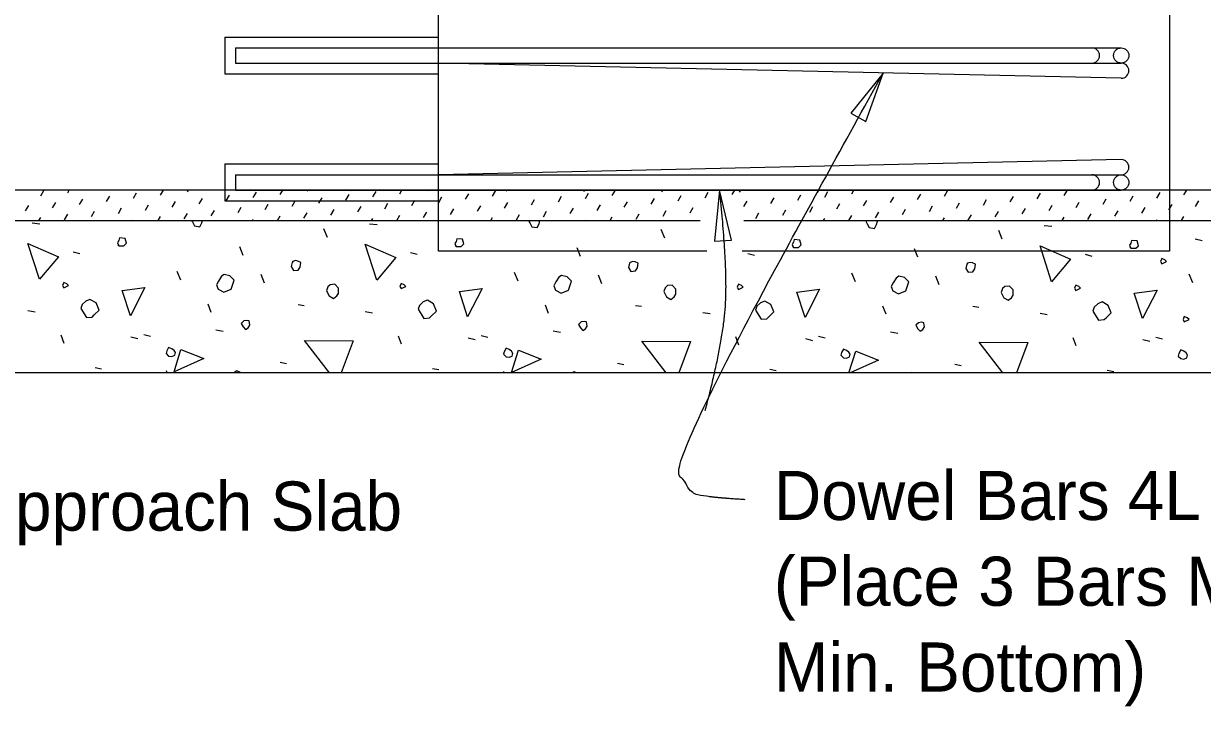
# Model space of a CAD drawing. Extents: x 21587 to 21656.3, y 56114 to 56157.2.
# Drawn here: x 21619.146 to 21623.985, y 56131.933 to 56134.734 of the extents above; entities that cross this region are included whole.
import ezdxf

# ---------------------------------------------------------------- set-up
doc = ezdxf.new("R2010")
doc.units = 0
for name, color, linetype in [('AdhocPoint_dp', 7, 'Continuous'), ('PlotBorder_dp', 7, 'Continuous'), ('SheetBorder_dp', 7, 'Continuous'), ('SheetLines_dp', 7, 'Continuous'), ('SubStrConc', 7, 'Continuous'), ('SubStrConc_h', 7, 'Continuous'), ('TextMisc', 7, 'Continuous')]:
    doc.layers.add(name, color=color, linetype=linetype)

msp = doc.modelspace()

# ---------------------------------------------------------------- linework, layer by layer
at = {"layer": 'AdhocPoint_dp'}
for p, q in [((21619.9721, 56134.6787), (21619.9721, 56134.5273)), ((21619.9721, 56134.6787), (21620.8499, 56134.6787)), ((21619.9721, 56134.5273), (21620.8499, 56134.5273)), ((21619.9721, 56134.1579), (21620.8499, 56134.1579)), ((21619.9721, 56134.1579), (21619.9721, 56134.0065)), ((21624.3563, 56134.0511), (21613.608, 56134.0511)), ((21619.9721, 56134.0065), (21620.8499, 56134.0065)), ((21613.608, 56133.926), (21621.9231, 56133.926)), ((21622.1027, 56133.926), (21624.3563, 56133.926)), ((21624.3563, 56133.301), (21618.8279, 56133.301))]:
    msp.add_line(p, q, dxfattribs=at)
at = {"layer": 'PlotBorder_dp'}
for points in [[(21622.6748, 56134.5311), (21622.5424, 56134.3666), (21622.604, 56134.3322)], [(21622.0034, 56134.0509), (21621.9823, 56133.8408), (21622.0527, 56133.8455)]]:
    msp.add_lwpolyline(points, close=True, dxfattribs=at)
for points in [[(21622.109, 56132.7809), (21621.9358, 56132.7915), (21621.8722, 56132.8163), (21621.805, 56132.9754), (21622.6748, 56134.5311)], [(21621.9446, 56133.1469), (21622.0135, 56133.4067), (21622.0391, 56133.7156), (21622.0034, 56134.0509)]]:
    msp.add_open_spline(points, degree=2, dxfattribs=at)
at = {"layer": 'SheetLines_dp'}
for p, q in [((21620.0165, 56134.6343), (21623.652, 56134.6343)), ((21620.0165, 56134.6343), (21620.0165, 56134.5718)), ((21620.0165, 56134.5718), (21623.652, 56134.5718)), ((21623.652, 56134.5094), (21620.8499, 56134.5718)), ((21623.652, 56134.1758), (21620.8499, 56134.1134)), ((21620.0165, 56134.1134), (21623.652, 56134.1134)), ((21620.0165, 56134.1134), (21620.0165, 56134.0509)), ((21620.0165, 56134.0509), (21623.652, 56134.0509))]:
    msp.add_line(p, q, dxfattribs=at)
for centre in [(21623.652, 56134.603), (21623.652, 56134.0822)]:
    msp.add_circle(centre, 0.0312, dxfattribs=at)
for centre in [(21623.5317, 56134.603), (21623.652, 56134.5406), (21623.652, 56134.5406), (21623.652, 56134.1446), (21623.5317, 56134.0822)]:
    msp.add_arc(centre, 0.0312, 270, 90, dxfattribs=at)
at = {"layer": 'SubStrConc'}
for p, q in [((21620.8499, 56134.0509), (21620.8499, 56134.8009)), ((21623.8499, 56134.8009), (21623.8499, 56134.0509))]:
    msp.add_line(p, q, dxfattribs=at)
at = {"layer": 'SubStrConc_h'}
for points in [[(21621.9508, 56133.8009), (21620.8499, 56133.8009), (21620.8499, 56134.0509)], [(21623.8499, 56134.0509), (21623.8499, 56133.8009), (21622.0964, 56133.8009)]]:
    msp.add_lwpolyline(points, dxfattribs=at)
at = {"layer": 'TextMisc'}
for p, q in [((21619.2168, 56134.0271), (21619.2298, 56134.0495)), ((21619.3275, 56134.04), (21619.3339, 56134.0511)), ((21619.3763, 56133.9912), (21619.3893, 56134.0136)), ((21619.4869, 56134.0042), (21619.4999, 56134.0266)), ((21619.5976, 56134.0171), (21619.6105, 56134.0395)), ((21619.7082, 56134.0301), (21619.7204, 56134.0511)), ((21619.8188, 56134.0431), (21619.8235, 56134.0511)), ((21619.8677, 56133.9942), (21619.8806, 56134.0166)), ((21619.9783, 56134.0072), (21619.9913, 56134.0296)), ((21620.0889, 56134.0202), (21620.1019, 56134.0426)), ((21620.1692, 56134.0497), (21620.1699, 56134.0509)), ((21620.1996, 56134.0331), (21620.21, 56134.0511)), ((21620.3102, 56134.0461), (21620.3131, 56134.0511)), ((21620.359, 56133.9973), (21620.372, 56134.0196)), ((21620.4697, 56134.0102), (21620.4826, 56134.0326)), ((21620.4886, 56134.0485), (21620.49, 56134.0509)), ((21620.5803, 56134.0232), (21620.5933, 56134.0456)), ((21620.6909, 56134.0361), (21620.6996, 56134.0511)), ((21620.8016, 56134.0491), (21620.8027, 56134.0511)), ((21620.808, 56134.0474), (21620.81, 56134.0509)), ((21620.8504, 56134.0003), (21620.8634, 56134.0227)), ((21620.961, 56134.0132), (21620.974, 56134.0356)), ((21621.0717, 56134.0262), (21621.0846, 56134.0486)), ((21621.1274, 56134.0462), (21621.1301, 56134.0509)), ((21621.2311, 56133.9903), (21621.2441, 56134.0127)), ((21621.3418, 56134.0033), (21621.3547, 56134.0257)), ((21621.4468, 56134.045), (21621.4502, 56134.0509)), ((21621.4524, 56134.0163), (21621.4654, 56134.0386)), ((21621.563, 56134.0292), (21621.5757, 56134.0511)), ((21621.7225, 56133.9933), (21621.7355, 56134.0157)), ((21621.7661, 56134.0438), (21621.7702, 56134.0509)), ((21621.8331, 56134.0063), (21621.8461, 56134.0287)), ((21621.9438, 56134.0193), (21621.9567, 56134.0417)), ((21622.0544, 56134.0322), (21622.0653, 56134.0511)), ((21622.0855, 56134.0426), (21622.0903, 56134.0509)), ((21622.2139, 56133.9964), (21622.2268, 56134.0188)), ((21622.3245, 56134.0093), (21622.3375, 56134.0317)), ((21622.4049, 56134.0415), (21622.4103, 56134.0509)), ((21622.4351, 56134.0223), (21622.4481, 56134.0447)), ((21622.5458, 56134.0353), (21622.5549, 56134.0511)), ((21622.7052, 56133.9994), (21622.7182, 56134.0218)), ((21622.8159, 56134.0124), (21622.8288, 56134.0347)), ((21622.9265, 56134.0253), (21622.9395, 56134.0477)), ((21623.086, 56133.9894), (21623.0989, 56134.0118)), ((21623.1966, 56134.0024), (21623.2096, 56134.0248)), ((21623.3072, 56134.0154), (21623.3202, 56134.0378)), ((21623.4179, 56134.0283), (21623.4308, 56134.0507)), ((21623.5773, 56133.9925), (21623.5903, 56134.0149)), ((21623.688, 56134.0054), (21623.7009, 56134.0278)), ((21623.7986, 56134.0184), (21623.8116, 56134.0408)), ((21623.9092, 56134.0314), (21623.9206, 56134.0511)), ((21619.155, 56133.9653), (21619.168, 56133.9877)), ((21619.2657, 56133.9782), (21619.2786, 56134.0006)), ((21619.4251, 56133.9424), (21619.4381, 56133.9648)), ((21619.5358, 56133.9553), (21619.5487, 56133.9777)), ((21619.6464, 56133.9683), (21619.6594, 56133.9907)), ((21619.757, 56133.9813), (21619.77, 56134.0037)), ((21619.9165, 56133.9454), (21619.9295, 56133.9678)), ((21620.0271, 56133.9584), (21620.0401, 56133.9808)), ((21620.1378, 56133.9713), (21620.1507, 56133.9937)), ((21620.2484, 56133.9843), (21620.2614, 56134.0067)), ((21620.4079, 56133.9484), (21620.4208, 56133.9708)), ((21620.5185, 56133.9614), (21620.5315, 56133.9838)), ((21620.6291, 56133.9743), (21620.6421, 56133.9967)), ((21620.7398, 56133.9873), (21620.7527, 56134.0097)), ((21620.8992, 56133.9514), (21620.9122, 56133.9738)), ((21621.0099, 56133.9644), (21621.0228, 56133.9868)), ((21621.1205, 56133.9774), (21621.1335, 56133.9998)), ((21621.28, 56133.9415), (21621.2929, 56133.9639)), ((21621.3906, 56133.9545), (21621.4036, 56133.9768)), ((21621.5012, 56133.9674), (21621.5142, 56133.9898)), ((21621.6119, 56133.9804), (21621.6248, 56134.0028)), ((21621.7713, 56133.9445), (21621.7843, 56133.9669)), ((21621.882, 56133.9575), (21621.8949, 56133.9799)), ((21622.1032, 56133.9834), (21622.1162, 56134.0058)), ((21622.2627, 56133.9475), (21622.2757, 56133.9699)), ((21622.3733, 56133.9605), (21622.3863, 56133.9829)), ((21622.484, 56133.9735), (21622.4969, 56133.9959)), ((21622.5946, 56133.9864), (21622.6076, 56134.0088)), ((21622.7541, 56133.9506), (21622.767, 56133.9729)), ((21622.8647, 56133.9635), (21622.8777, 56133.9859)), ((21622.9753, 56133.9765), (21622.9883, 56133.9989)), ((21623.1348, 56133.9406), (21623.1478, 56133.963)), ((21623.2454, 56133.9536), (21623.2584, 56133.976)), ((21623.3561, 56133.9665), (21623.369, 56133.9889)), ((21623.4667, 56133.9795), (21623.4797, 56134.0019)), ((21623.6262, 56133.9436), (21623.6391, 56133.966)), ((21623.7368, 56133.9566), (21623.7498, 56133.979)), ((21623.8474, 56133.9696), (21623.8604, 56133.9919)), ((21623.9571, 56133.9838), (21623.97, 56134.0062)), ((21619.1816, 56133.9165), (21619.2134, 56133.913)), ((21619.2094, 56133.926), (21619.2168, 56133.9388)), ((21619.3145, 56133.9294), (21619.3275, 56133.9518)), ((21619.5959, 56133.926), (21619.5976, 56133.9289)), ((21619.699, 56133.926), (21619.7082, 56133.9419)), ((21619.8059, 56133.9324), (21619.8188, 56133.9548)), ((21620.0855, 56133.926), (21620.0889, 56133.9319)), ((21620.1886, 56133.926), (21620.1996, 56133.9449)), ((21620.2972, 56133.9355), (21620.3102, 56133.9578)), ((21620.5751, 56133.926), (21620.5803, 56133.9349)), ((21620.6783, 56133.926), (21620.6909, 56133.9479)), ((21620.7886, 56133.9385), (21620.8016, 56133.9609)), ((21621.0648, 56133.926), (21621.0717, 56133.938)), ((21621.1693, 56133.9285), (21621.1823, 56133.9509)), ((21621.4512, 56133.926), (21621.4524, 56133.928)), ((21621.5544, 56133.926), (21621.563, 56133.941)), ((21621.6607, 56133.9315), (21621.6737, 56133.9539)), ((21622.1521, 56133.9346), (21622.165, 56133.957)), ((21622.4305, 56133.926), (21622.4351, 56133.9341)), ((21622.5336, 56133.926), (21622.5458, 56133.947)), ((21622.6434, 56133.9376), (21622.6564, 56133.96)), ((21622.9201, 56133.926), (21622.9265, 56133.9371)), ((21623.0242, 56133.9276), (21623.0371, 56133.95)), ((21623.3066, 56133.926), (21623.3072, 56133.9271)), ((21623.4097, 56133.926), (21623.4179, 56133.9401)), ((21623.5155, 56133.9307), (21623.5285, 56133.9531)), ((21623.7962, 56133.926), (21623.7986, 56133.9302)), ((21623.8993, 56133.926), (21623.9092, 56133.9431)), ((21620.3937, 56133.857), (21620.3795, 56133.8924)), ((21620.5663, 56133.913), (21620.5981, 56133.9094)), ((21621.7784, 56133.8535), (21621.7642, 56133.8889)), ((21623.163, 56133.85), (21623.1489, 56133.8853)), ((21623.3356, 56133.9059), (21623.3675, 56133.9024)), ((21620.0478, 56133.7822), (21620.0337, 56133.8175)), ((21623.9556, 56133.8507), (21623.9839, 56133.8437)), ((21619.3496, 56133.7981), (21619.3778, 56133.791)), ((21620.7342, 56133.7945), (21620.7625, 56133.7875)), ((21621.4325, 56133.7786), (21621.4184, 56133.814)), ((21622.1189, 56133.791), (21622.1472, 56133.7839)), ((21622.8172, 56133.7751), (21622.803, 56133.8104)), ((21623.5036, 56133.7875), (21623.5319, 56133.7804)), ((21619.7915, 56133.6814), (21619.7774, 56133.7168)), ((21620.1356, 56133.6697), (21620.1214, 56133.705)), ((21621.1762, 56133.6779), (21621.162, 56133.7132)), ((21621.5203, 56133.6661), (21621.5061, 56133.7015)), ((21622.5609, 56133.6743), (21622.5467, 56133.7097)), ((21622.9049, 56133.6626), (21622.8908, 56133.6979)), ((21623.9455, 56133.6708), (21623.9314, 56133.7062)), ((21619.917, 56133.5488), (21619.9046, 56133.5824)), ((21620.2735, 56133.5813), (21620.2982, 56133.5777)), ((21621.3017, 56133.5453), (21621.2893, 56133.5789)), ((21621.6581, 56133.5777), (21621.6829, 56133.5742)), ((21622.6864, 56133.5417), (21622.674, 56133.5753)), ((21619.1646, 56133.5565), (21619.1946, 56133.5512)), ((21620.5492, 56133.553), (21620.5793, 56133.5477)), ((21621.9339, 56133.5494), (21621.964, 56133.5441)), ((21623.0428, 56133.5742), (21623.0676, 56133.5707)), ((21623.3186, 56133.5459), (21623.3486, 56133.5406)), ((21619.3131, 56133.4222), (21619.3007, 56133.4558)), ((21619.5871, 56133.4487), (21619.6153, 56133.4416)), ((21619.6395, 56133.4587), (21619.6678, 56133.4516)), ((21619.9358, 56133.477), (21619.9659, 56133.4717)), ((21620.6977, 56133.4186), (21620.6854, 56133.4522)), ((21620.9717, 56133.4451), (21621, 56133.4381)), ((21621.0241, 56133.4551), (21621.0524, 56133.4481)), ((21621.3205, 56133.4734), (21621.3506, 56133.4681)), ((21622.0824, 56133.4151), (21622.07, 56133.4487)), ((21622.3564, 56133.4416), (21622.3847, 56133.4345)), ((21622.4088, 56133.4516), (21622.4371, 56133.4445)), ((21622.7052, 56133.4699), (21622.7352, 56133.4646)), ((21623.4671, 56133.4116), (21623.4547, 56133.4451)), ((21623.7411, 56133.4381), (21623.7694, 56133.431)), ((21623.7935, 56133.4481), (21623.8218, 56133.441)), ((21620.1992, 56133.3444), (21620.2257, 56133.3391)), ((21621.5839, 56133.3408), (21621.6104, 56133.3355)), ((21622.9686, 56133.3373), (21622.9951, 56133.332)), ((21619.4403, 56133.3232), (21619.4669, 56133.3179)), ((21619.7364, 56133.301), (21619.7332, 56133.3097)), ((21620.825, 56133.3196), (21620.8515, 56133.3143)), ((21621.1197, 56133.301), (21621.1178, 56133.3061)), ((21622.2097, 56133.3161), (21622.2362, 56133.3108)), ((21622.5031, 56133.301), (21622.5025, 56133.3026)), ((21623.5944, 56133.3126), (21623.6209, 56133.3073))]:
    msp.add_line(p, q, dxfattribs=at)
for points in [[(21619.8362, 56133.926), (21619.8392, 56133.9201)], [(21619.8392, 56133.9201), (21619.8481, 56133.9041), (21619.8693, 56133.9006), (21619.8781, 56133.9165), (21619.8805, 56133.926)], [(21621.2212, 56133.926), (21621.2204, 56133.9236), (21621.2239, 56133.9165)], [(21621.2239, 56133.9165), (21621.2327, 56133.9006), (21621.254, 56133.8971), (21621.2628, 56133.913), (21621.2661, 56133.926)], [(21622.607, 56133.926), (21622.605, 56133.9201), (21622.6086, 56133.913)], [(21622.6086, 56133.913), (21622.6174, 56133.8971), (21622.6386, 56133.8935), (21622.6475, 56133.9094), (21622.651, 56133.9236), (21622.6486, 56133.926)], [(21619.2123, 56133.6856), (21619.1646, 56133.8323), (21619.2901, 56133.7775), (21619.2123, 56133.6856)], [(21619.5369, 56133.8228), (21619.5582, 56133.8228), (21619.5688, 56133.8334), (21619.5635, 56133.8529), (21619.5405, 56133.8546), (21619.5369, 56133.844), (21619.5316, 56133.8352), (21619.5369, 56133.8228), (21619.5334, 56133.8264)], [(21620.597, 56133.682), (21620.5492, 56133.8288), (21620.6748, 56133.774), (21620.597, 56133.682)], [(21620.9216, 56133.8193), (21620.9428, 56133.8193), (21620.9534, 56133.8299), (21620.9481, 56133.8493), (21620.9252, 56133.8511), (21620.9216, 56133.8405), (21620.9163, 56133.8317), (21620.9216, 56133.8193), (21620.9181, 56133.8228)], [(21622.3063, 56133.8158), (21622.3275, 56133.8158), (21622.3381, 56133.8264), (21622.3328, 56133.8458), (21622.3098, 56133.8476), (21622.3063, 56133.837), (21622.301, 56133.8281), (21622.3063, 56133.8158), (21622.3028, 56133.8193)], [(21623.3663, 56133.675), (21623.3186, 56133.8217), (21623.4441, 56133.7669), (21623.3663, 56133.675)], [(21623.691, 56133.8122), (21623.7122, 56133.8122), (21623.7228, 56133.8228), (21623.7175, 56133.8423), (21623.6945, 56133.844), (21623.691, 56133.8334), (21623.6857, 56133.8246), (21623.691, 56133.8122), (21623.6874, 56133.8158)], [(21623.8185, 56133.7486), (21623.8379, 56133.7574), (21623.8308, 56133.7645), (21623.8185, 56133.7698), (21623.8132, 56133.7574), (21623.8185, 56133.7486)], [(21620.2452, 56133.7368), (21620.254, 56133.7209), (21620.2735, 56133.7227), (21620.2823, 56133.7351), (21620.2841, 56133.7545), (21620.2717, 56133.7598), (21620.2629, 56133.7616), (21620.2523, 56133.758), (21620.2487, 56133.7545), (21620.2452, 56133.7368)], [(21621.6299, 56133.7333), (21621.6387, 56133.7174), (21621.6581, 56133.7192), (21621.667, 56133.7315), (21621.6688, 56133.751), (21621.6564, 56133.7563), (21621.6475, 56133.758), (21621.6369, 56133.7545), (21621.6334, 56133.751), (21621.6299, 56133.7333)], [(21623.0145, 56133.7298), (21623.0234, 56133.7138), (21623.0428, 56133.7156), (21623.0517, 56133.728), (21623.0534, 56133.7474), (21623.0411, 56133.7527), (21623.0322, 56133.7545), (21623.0216, 56133.751), (21623.0181, 56133.7474), (21623.0145, 56133.7298)], [(21619.9453, 56133.6443), (21619.9683, 56133.6319), (21619.9983, 56133.6443), (21620.0107, 56133.6814), (21619.993, 56133.6991), (21619.97, 56133.7044), (21619.9594, 56133.6973), (21619.9471, 56133.6779), (21619.9382, 56133.662), (21619.9453, 56133.6443)], [(21621.33, 56133.6407), (21621.353, 56133.6284), (21621.383, 56133.6407), (21621.3954, 56133.6779), (21621.3777, 56133.6955), (21621.3547, 56133.7008), (21621.3441, 56133.6938), (21621.3317, 56133.6743), (21621.3229, 56133.6584), (21621.33, 56133.6407)], [(21622.7146, 56133.6372), (21622.7376, 56133.6248), (21622.7677, 56133.6372), (21622.7801, 56133.6743), (21622.7624, 56133.692), (21622.7394, 56133.6973), (21622.7288, 56133.6902), (21622.7164, 56133.6708), (21622.7076, 56133.6549), (21622.7146, 56133.6372)], [(21619.3113, 56133.6502), (21619.3307, 56133.659), (21619.3237, 56133.6661), (21619.3113, 56133.6714), (21619.306, 56133.659), (21619.3113, 56133.6502)], [(21619.5847, 56133.5347), (21619.5511, 56133.639), (21619.6448, 56133.6514), (21619.5847, 56133.5347)], [(21620.3901, 56133.6378), (21620.4008, 56133.6166), (21620.4184, 56133.606), (21620.4326, 56133.6166), (21620.4396, 56133.6272), (21620.4396, 56133.6484), (21620.4237, 56133.6644), (21620.4043, 56133.6626), (21620.3954, 56133.6537), (21620.3901, 56133.6378)], [(21620.696, 56133.6467), (21620.7154, 56133.6555), (21620.7083, 56133.6626), (21620.696, 56133.6679), (21620.6907, 56133.6555), (21620.696, 56133.6467)], [(21620.9693, 56133.5311), (21620.9358, 56133.6354), (21621.0294, 56133.6478), (21620.9693, 56133.5311)], [(21621.7748, 56133.6343), (21621.7854, 56133.6131), (21621.8031, 56133.6025), (21621.8172, 56133.6131), (21621.8243, 56133.6237), (21621.8243, 56133.6449), (21621.8084, 56133.6608), (21621.789, 56133.659), (21621.7801, 56133.6502), (21621.7748, 56133.6343)], [(21622.0806, 56133.6431), (21622.1001, 56133.652), (21622.093, 56133.659), (21622.0806, 56133.6644), (21622.0753, 56133.652), (21622.0806, 56133.6431)], [(21622.354, 56133.5276), (21622.3204, 56133.6319), (21622.4141, 56133.6443), (21622.354, 56133.5276)], [(21623.1595, 56133.6308), (21623.1701, 56133.6096), (21623.1878, 56133.5989), (21623.2019, 56133.6096), (21623.209, 56133.6202), (21623.209, 56133.6414), (21623.1931, 56133.6573), (21623.1736, 56133.6555), (21623.1648, 56133.6467), (21623.1595, 56133.6308)], [(21623.4653, 56133.6396), (21623.4848, 56133.6484), (21623.4777, 56133.6555), (21623.4653, 56133.6608), (21623.46, 56133.6484), (21623.4653, 56133.6396)], [(21623.7387, 56133.5241), (21623.7051, 56133.6284), (21623.7988, 56133.6407), (21623.7387, 56133.5241)], [(21619.382, 56133.5654), (21619.405, 56133.5282), (21619.428, 56133.53), (21619.4368, 56133.5388), (21619.4562, 56133.5583), (21619.4439, 56133.5883), (21619.4191, 56133.6025), (21619.4014, 56133.5954), (21619.3873, 56133.5813), (21619.382, 56133.5654)], [(21620.7667, 56133.5618), (21620.7897, 56133.5247), (21620.8126, 56133.5265), (21620.8215, 56133.5353), (21620.8409, 56133.5547), (21620.8285, 56133.5848), (21620.8038, 56133.5989), (21620.7861, 56133.5919), (21620.772, 56133.5777), (21620.7667, 56133.5618)], [(21622.1514, 56133.5583), (21622.1743, 56133.5212), (21622.1973, 56133.5229), (21622.2062, 56133.5318), (21622.2256, 56133.5512), (21622.2132, 56133.5813), (21622.1885, 56133.5954), (21622.1708, 56133.5883), (21622.1567, 56133.5742), (21622.1514, 56133.5583)], [(21623.536, 56133.5547), (21623.559, 56133.5176), (21623.582, 56133.5194), (21623.5908, 56133.5282), (21623.6103, 56133.5477), (21623.5979, 56133.5777), (21623.5732, 56133.5919), (21623.5555, 56133.5848), (21623.5413, 56133.5707), (21623.536, 56133.5547)], [(21623.9109, 56133.5108), (21623.9303, 56133.5197), (21623.9232, 56133.5267), (21623.9109, 56133.5321), (21623.9056, 56133.5197), (21623.9109, 56133.5108)], [(21620.0472, 56133.4893), (21620.0578, 56133.4787), (21620.0684, 56133.4858), (21620.0755, 56133.4964), (21620.0719, 56133.5141), (21620.0631, 56133.5159), (21620.0507, 56133.5141), (21620.0401, 56133.5035), (21620.0472, 56133.4893)], [(21621.4319, 56133.4858), (21621.4425, 56133.4752), (21621.4531, 56133.4823), (21621.4602, 56133.4929), (21621.4566, 56133.5106), (21621.4478, 56133.5123), (21621.4354, 56133.5106), (21621.4248, 56133.4999), (21621.4319, 56133.4858)], [(21622.8166, 56133.4823), (21622.8272, 56133.4717), (21622.8378, 56133.4787), (21622.8448, 56133.4893), (21622.8413, 56133.507), (21622.8325, 56133.5088), (21622.8201, 56133.507), (21622.8095, 56133.4964), (21622.8166, 56133.4823)], [(21620.4015, 56133.301), (21620.3, 56133.4345), (21620.4997, 56133.4328), (21620.4505, 56133.301)], [(21621.7835, 56133.301), (21621.6847, 56133.431), (21621.8844, 56133.4292), (21621.8365, 56133.301)], [(21619.742, 56133.3703), (21619.7544, 56133.3685), (21619.7667, 56133.3738), (21619.7703, 56133.3844), (21619.765, 56133.3933), (21619.7544, 56133.4003), (21619.742, 56133.4056), (21619.7349, 56133.3915), (21619.7314, 56133.3809), (21619.742, 56133.3703)], [(21619.7644, 56133.3055), (21619.7926, 56133.3974), (21619.8863, 56133.3603), (21619.7644, 56133.3055)], [(21621.1267, 56133.3667), (21621.1391, 56133.365), (21621.1514, 56133.3703), (21621.155, 56133.3809), (21621.1497, 56133.3897), (21621.1391, 56133.3968), (21621.1267, 56133.4021), (21621.1196, 56133.388), (21621.1161, 56133.3773), (21621.1267, 56133.3667)], [(21621.149, 56133.302), (21621.1773, 56133.3939), (21621.271, 56133.3568), (21621.149, 56133.302)], [(21622.5114, 56133.3632), (21622.5237, 56133.3614), (21622.5361, 56133.3667), (21622.5396, 56133.3773), (21622.5343, 56133.3862), (21622.5237, 56133.3933), (21622.5114, 56133.3986), (21622.5043, 56133.3844), (21622.5007, 56133.3738), (21622.5114, 56133.3632)], [(21622.5345, 56133.301), (21622.562, 56133.3903), (21622.6557, 56133.3532), (21622.5394, 56133.301)], [(21623.1655, 56133.301), (21623.0693, 56133.4275), (21623.2691, 56133.4257), (21623.2225, 56133.301)], [(21623.896, 56133.3597), (21623.9084, 56133.3579), (21623.9208, 56133.3632), (21623.9243, 56133.3738), (21623.919, 56133.3827), (21623.9084, 56133.3897), (21623.896, 56133.395), (21623.889, 56133.3809), (21623.8854, 56133.3703), (21623.896, 56133.3597)], [(21620.0368, 56133.301), (21620.0366, 56133.302), (21620.0224, 56133.309), (21620.009, 56133.301)], [(21621.4161, 56133.301), (21621.4071, 56133.3055), (21621.3996, 56133.301)], [(21622.7937, 56133.301), (21622.7918, 56133.302), (21622.7902, 56133.301)]]:
    msp.add_lwpolyline(points, dxfattribs=at)

# ---------------------------------------------------------------- texts
at = {"layer": 'PlotBorder_dp'}
for s, p in [('Dowel Bars 4L (10" Embedment) ', (21622.226, 56132.6977)), ('(Place 3 Bars Min. Top and 1 Bar ', (21622.226, 56132.3457)), ('Min. Bottom)', (21622.226, 56131.9937))]:
    msp.add_text(s, height=0.2016, dxfattribs=at).set_placement(p)
at = {"layer": 'SheetBorder_dp'}
msp.add_text('Existing Approach Slab', height=0.2016, dxfattribs=at).set_placement((21617.9127, 56132.654))

doc.saveas('drawing.dxf')
